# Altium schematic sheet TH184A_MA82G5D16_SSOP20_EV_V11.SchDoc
size 292 x 203 mm
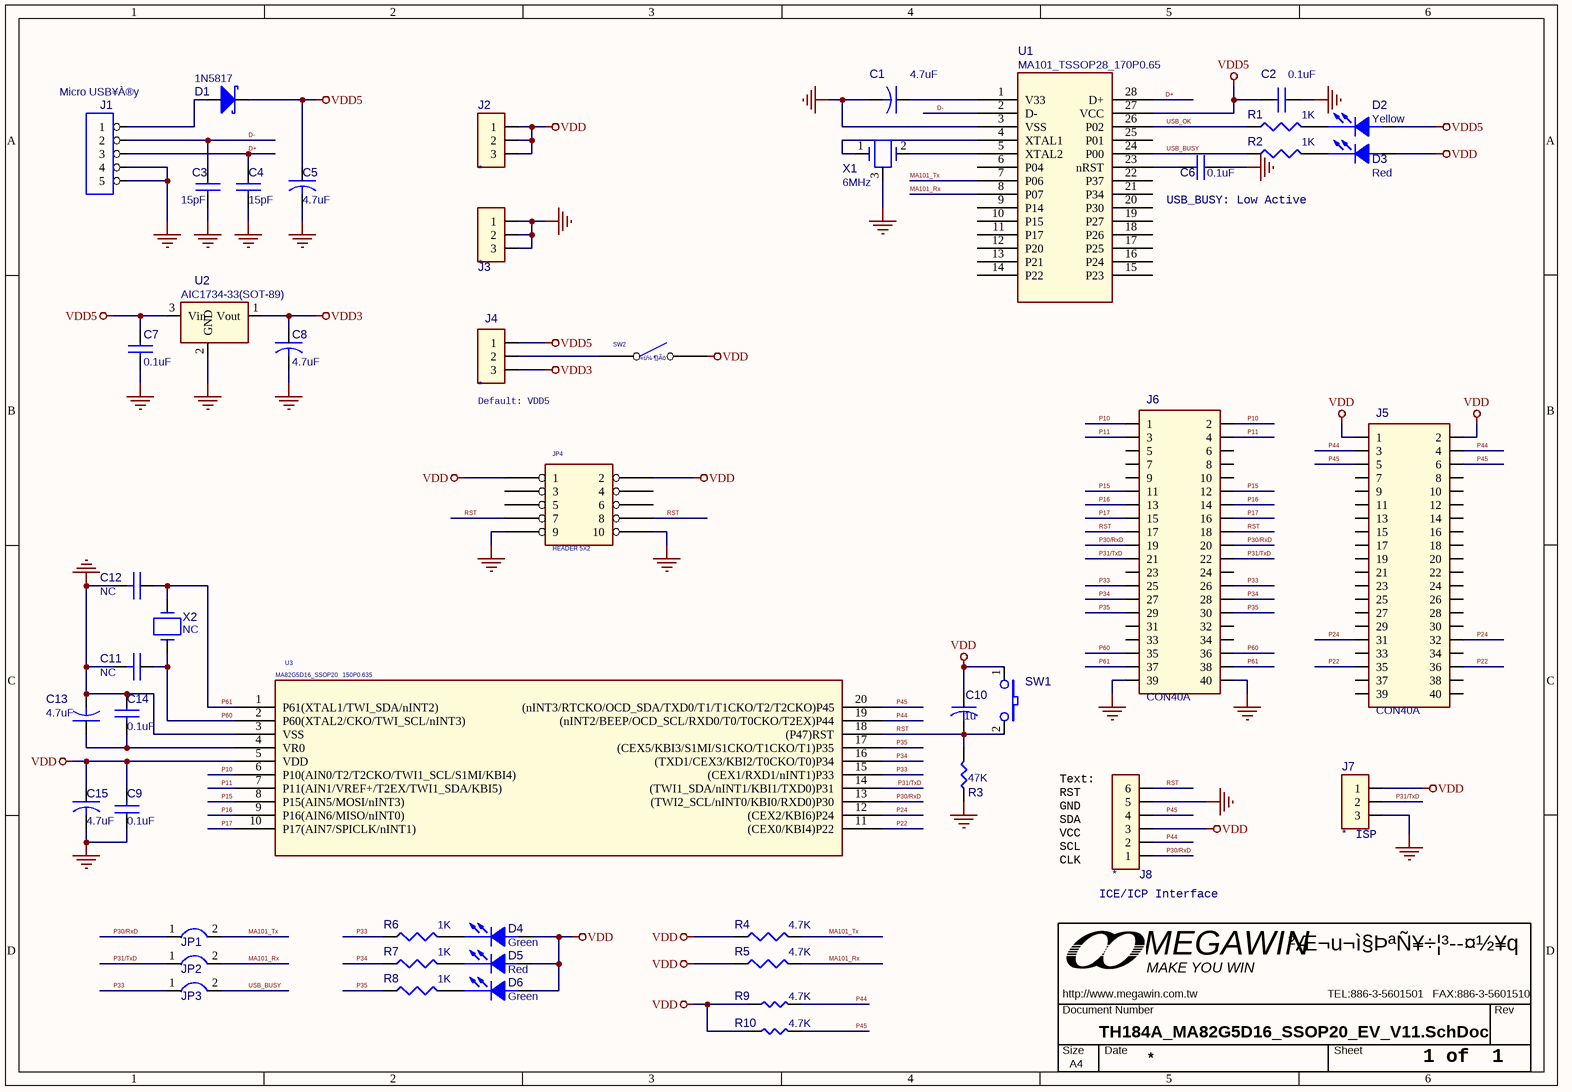
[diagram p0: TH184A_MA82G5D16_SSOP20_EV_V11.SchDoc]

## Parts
C1  4.7uF  [0805C]
C2  0.1uF  [0805C]
C3  15pF  [0805C]
C4  15pF  [0805C]
C5  4.7uF  [1206C]
C6  0.1uF  [0805C]
C7  0.1uF  [0805C]
C8  4.7uF  [0805C]
C9  0.1uF  [0805C]
C10  1u  [0805C]
C11  NC  [0805C]
C12  NC  [0805C]
C13  4.7uF  [0805C]
C14  0.1uF  [0805C]
C15  4.7uF  [0805C]
D1  1N5817  [D5817_SMD_1]
D2  Yellow  [0805D]
D3  Red  [0805D]
D4  Green  [0805D]
D5  Red  [0805D]
D6  Green  [0805D]
J1  Micro USB¥À®y  [JACK_USB_SMD290X220P065]
J2  *  [PS3P254]
J3  *  [PS3P254]
J4  *  [JUMP3_SMD]
J5  CON40A  [PS20X2P254]
J6  CON40A  [PS20X2P254]
J7  *  [PS3P254f_90]
J8  *  [PS6P254F_90]
JP1  JUMPER2  [PS2P254]  (value not drawn)
JP2  JUMPER2  [PS2P254]  (value not drawn)
JP3  JUMPER2  [PS2P254]  (value not drawn)
JP4  HEADER 5X2  [PS5X2P254]
MW1  OrgName: ²Æ¬u¬ì§ÞªÑ¥÷¦³­­¤½¥q  OrgAddr1: MEGAWIN  OrgAddr3: TEL:886-3-5601501   FAX:886-3-5601510  Page Size: A4  [MEGAWIN_T]  (hidden comment: MW-A4)  (no BOM)
R1  1K  [0805R]
R2  1K  [0805R]
R3  47K  [0805R]
R4  4.7K  [0805R]
R5  4.7K  [0805R]
R6  1K  [0805R]
R7  1K  [0805R]
R8  1K  [0805R]
R9  4.7K  [0805R]
R10  4.7K  [0805R]
SW1  SW TACT-SPST  [SW_T_2P]  (value not drawn)
SW2  «ü¼·¶}Ãö  [DIP2_SW]
U1  MA101_TSSOP28_170P0.65  [TSSOP28_170P065]
U2  AIC1734-33(SOT-89)  [SOT89]
U3  MA82G5D16_SSOP20   150P0.635  [SSOP20_150P0635]
X1  6MHz  [X3P]
X2  NC  [X49U]

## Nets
GND_POWER: C1.2 C2.1 C3.2 C4.2 C5.2 C6.1 C7.2 C8.2 C9.1 C11.2 C12.2 C13.2 C14.1 C15.2 J1.4 J1.5 J3.1 J3.2 J3.3 J6.39 J6.40 J7.3 J8.5 JP4.9 JP4.10 R3.1 U1.3(VSS) U2.2(GND) U3.3(VSS) X1.3
VDD: C9.2 C10.1(POS) C15.1 D3.1(ANODE) D4.1(ANODE) D5.1(ANODE) D6.1(ANODE) J2.1 J2.2 J2.3 J5.1 J5.2 J7.1 J8.3 JP4.1 JP4.2 R4.1 R5.1 R9.2 R10.2 SW1.1 SW2.2 U3.5(VDD)
VDD3: C8.1 J4.3 U2.1(Vout)
VDD5: C2.2 C5.1 C7.1 D1.2(K) D2.1(ANODE) J4.1 U1.27(VCC) U2.3(Vin)
D+: C4.1 J1.3 U1.28(D+)
D-: C3.1 J1.2 U1.2(D-)
MA101_Rx: JP2.2 R5.2 U1.8(P07)
MA101_Tx: JP1.2 R4.2 U1.7(P06)
P10: J6.1 J6.2 U3.6(P10(AIN0/T2/T2CKO/TWI1_SCL/S1MI/KBI4))
P11: J6.3 J6.4 U3.7(P11(AIN1/VREF+/T2EX/TWI1_SDA/KBI5))
P15: J6.11 J6.12 U3.8(P15(AIN5/MOSI/nINT3))
P16: J6.13 J6.14 U3.9(P16(AIN6/MISO/nINT0))
P17: J6.15 J6.16 U3.10(P17(AIN7/SPICLK/nINT1))
P22: J5.35 J5.36 U3.11((CEX0/KBI4)P22)
P24: J5.31 J5.32 U3.12((CEX2/KBI6)P24)
P30/RxD: J6.19 J6.20 J8.1 JP1.1 U3.13((TWI2_SCL/nINT0/KBI0/RXD0)P30)
P31/TxD: J6.21 J6.22 J7.2 JP2.1 U3.14((TWI1_SDA/nINT1/KBI1/TXD0)P31)
P33: J6.25 J6.26 JP3.1 R6.1 U3.15((CEX1/RXD1/nINT1)P33)
P34: J6.27 J6.28 R7.1 U3.16((TXD1/CEX3/KBI2/T0CKO/T0)P34)
P35: J6.29 J6.30 R8.1 U3.17((CEX5/KBI3/S1MI/S1CKO/T1CKO/T1)P35)
P44: J5.3 J5.4 J8.2 R9.1 U3.19((nINT2/BEEP/OCD_SCL/RXD0/T0/T0CKO/T2EX)P44)
P45: J5.5 J5.6 J8.4 R10.1 U3.20((nINT3/RTCKO/OCD_SDA/TXD0/T1/T1CKO/T2/T2CKO)P45)
P60: C11.1 J6.35 J6.36 U3.2(P60(XTAL2/CKO/TWI_SCL/nINT3)) X2.1
P61: C12.1 J6.37 J6.38 U3.1(P61(XTAL1/TWI_SDA/nINT2)) X2.2
RST: C10.2(NEG) J6.17 J6.18 J8.6 JP4.7 JP4.8 R3.2 SW1.2 U3.18((P47)RST)
USB_BUSY: JP3.2 R2.1 U1.24(P00)
USB_OK: R1.1 U1.26(P02)
NetC1_1: C1.1 U1.1(V33)
NetC6_2: C6.2 U1.23(nRST)
NetC13_1: C13.1 C14.2 U3.4(VR0)
NetD1_1: D1.1(A) J1.1
NetD2_2: D2.2(CATHODE) R1.2
NetD3_2: D3.2(CATHODE) R2.2
NetD4_2: D4.2(CATHODE) R6.2
NetD5_2: D5.2(CATHODE) R7.2
NetD6_2: D6.2(CATHODE) R8.2
NetJ4_2: J4.2 SW2.1
NetU1_4: U1.4(XTAL1) X1.1
NetU1_5: U1.5(XTAL2) X1.2

Not connected (* = marked no-connect by the designer): J5 7 8 9 10 11 12 13 14 15 16 17 18 19 20 21 22 23 24 25 26 27 28 29 30 33 34 37 38 39 40; J6 5 6 7 8 9 10 23 24 31 32 33 34; JP4 3 4 5 6; U1 6(P04) 9(P14) 10(P15) 11(P17) 12(P20) 13(P21) 14(P22) 15(P23) 16(P24) 17(P25) 18(P26) 19(P27) 20(P30) 21(P34) 22(P37) 25(P01)

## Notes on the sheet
- USB_BUSY: Low Active
- (near J4) Default: VDD5
- (near J7) ISP
- Text:
  RST
  GND
  SDA
  VCC
  SCL
  CLK
- ICE/ICP Interface
- 1 of  1

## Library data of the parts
C1 C5 C8 C13 C15 = CAP
C2-C4 C6 C7 C9 C14 = CAP NP
C10 = C
C11 C12 = C NP
D1 = DIODE_ZD: Schottky Diode
D2-D6 = LED
J1 = CON5: Connector
J2-J4 J7 = CON3
J8 = CON6
R1 R2 R4-R8 = R_Dup1
R3 R9 R10 = R
SW2 = SW SPST
U1 = MA101_TSSOP28
U2 = AIC1734-33(SOT-89)_0
U3 = MG82FG5Dxx_SSOP-20
X1 = CRYSTAL_RC
X2 = CRYSTAL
